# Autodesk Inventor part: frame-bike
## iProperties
Author: Administrator
Created: 2001-03
Part Number: frame-bike
Document SubType Name: Modeling
Designer: Administrator
Control State: 0
Master: False
Checked Out: False
PropertySet Name: Design Tracking Control
Shininess: 20.0
PropertySet Name: _Private Model Information
Density: 0.0
Volumn: 0.0
Area: 0.0
PropertySet Name: Model Information
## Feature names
1. Extrusion1
2. Fillet1
3. Extrusion2
4. Extrusion3
5. Extrusion4
6. Extrusion5
7. Extrusion6
8. Fillet4
9. Extrusion7
10. Extrusion8
11. Extrusion9
12. Fillet5
13. Extrusion10
14. Extrusion11
15. Extrusion12
16. Fillet6
17. Extrusion13
18. Mirror1
19. Extrusion14
20. Chamfer1
21. Hole1
22. Revolution2
23. Circular Pattern1
24. Fillet7
25. Fillet8
26. Extrusion15
27. Revolution4
28. Fillet9
